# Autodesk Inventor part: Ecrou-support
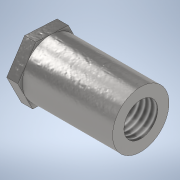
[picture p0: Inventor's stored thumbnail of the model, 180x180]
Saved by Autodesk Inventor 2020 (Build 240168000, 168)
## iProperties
Created: 2021-10
Part Number: Ecrou-support
Material: Générique
Document SubType Name: Modeling
Designer: bruno
Density: 1 g/cm^3
Appearance: Galvanisé
Author: bruno
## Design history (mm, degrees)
sketch "Esquisse1"
  geometry: L1 (-2.577, -1.3)-(-2.415, 1.582); L2 (-2.415, 1.582)-(0.163, 2.882); L3 (0.163, 2.882)-(2.577, 1.3); L4 (2.577, 1.3)-(2.415, -1.582); L5 (2.415, -1.582)-(-0.163, -2.882); L6 (-0.163, -2.882)-(-2.577, -1.3); 2 further points
  constraints: 12 end point, 1 coincident, 13 other
  dimensions: "d0" = 5 distance between parallel lines of L5 L2
extrude "Extrusion1" new body sketch "Esquisse1" distance "d1" = 1; taper "d2" = 0 deg
sketch "Esquisse2"
  geometry: L1 (1.582, 2.415)-(-1.3, 2.577) reference; C1 r 2.5 at (0, 0); 1 further point
  constraints: 1 centre point, 1 coincident, 1 tangent
extrude "Extrusion2" join sketch "Esquisse2" distance "d3" = 8; taper "d4" = 0 deg
sketch "Esquisse3"
  geometry: C1 r 1.5 at (0.003, 0.002); 1 further point
  constraints: 1 centre point
  dimensions: "d5" = 3 diameter of C1
extrude "Extrusion3" cut sketch "Esquisse3" distance "d6" = 15; taper "d7" = 0 deg
feature "Filetage1" dims "d8" = 10, "d9" = 0
node "Solide1"
